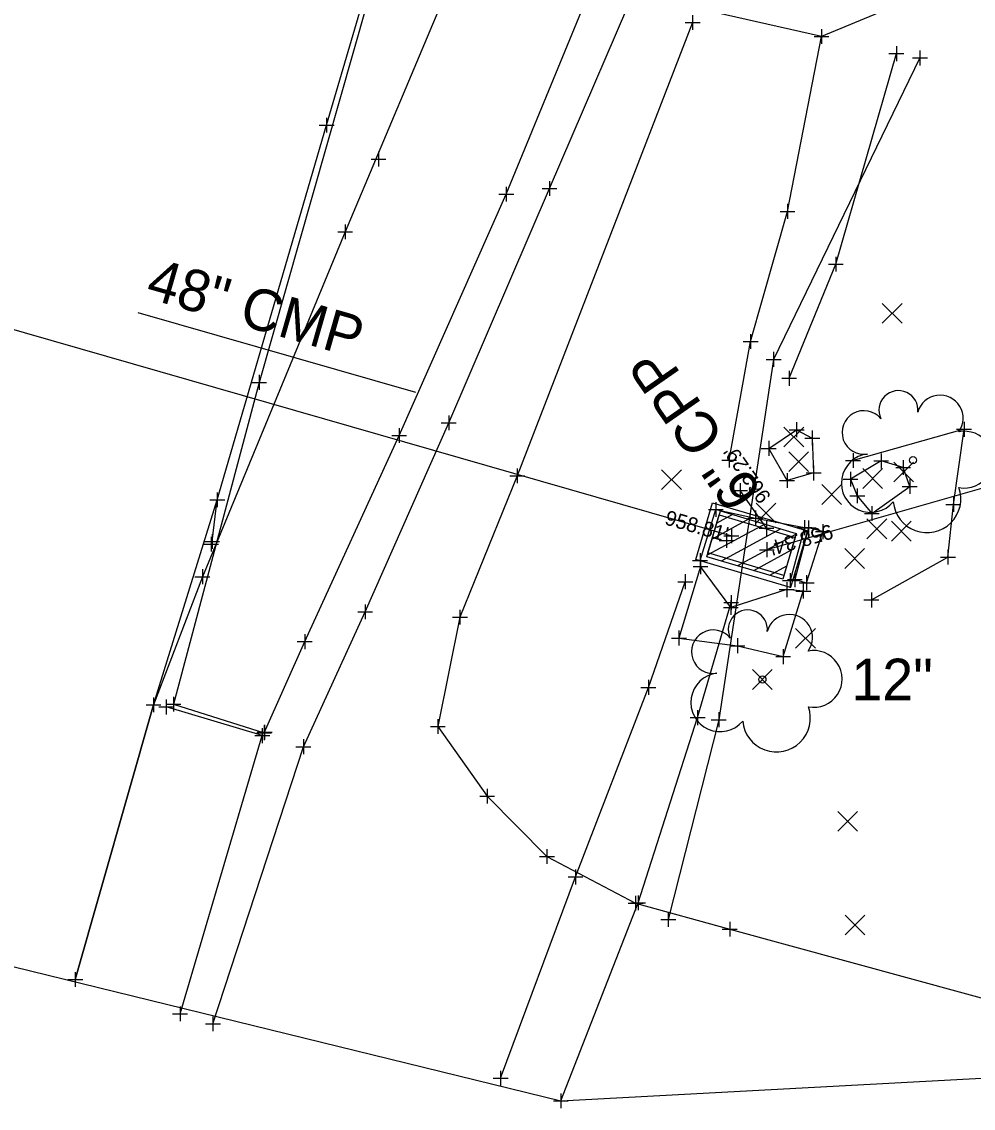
# Model space of a CAD drawing. Extents: x 160138 to 160780, y 488720 to 491073.
# Drawn here: x 160437.1 to 160501.3, y 489628.4 to 489701.6 of the extents above; entities that cross this region are included whole.
import ezdxf

# ---------------------------------------------------------------- set-up
doc = ezdxf.new("R2010")
doc.units = 0
for name, color, linetype in [('_CIVIL_CONSTRUCTION', 7, 'Continuous'), ('DR_X_Storm_Sewer', 7, 'Continuous'), ('DR_X_Text', 7, 'Continuous'), ('GE_X_Alignment_500_Bearings', 7, 'Continuous'), ('GE_X_Alignment_500_Stations', 7, 'Continuous'), ('PM_X_Dotted_Line', 7, 'Continuous'), ('PM_X_Lane_Line', 7, 'Continuous'), ('RD_X_Concrete_Pad', 7, 'Continuous'), ('RS_Raster1', 7, 'Continuous'), ('RW_X_CL', 7, 'Continuous'), ('RW_X_CL_100_Cardinal_Points', 7, 'Continuous'), ('RW_X_CL_100_Distances', 7, 'Continuous'), ('SC_Scratch1', 7, 'Continuous'), ('SV_P_Control_Cells_Set', 7, 'Continuous'), ('SV_P_Mon_Cells_Set', 7, 'Continuous'), ('SV_X_Control_Cells_Found', 7, 'Continuous'), ('SV_X_Random_Point', 7, 'Continuous'), ('SV_X_Terrain_Boundary', 7, 'Continuous'), ('UT_X_Electric', 7, 'Continuous'), ('VG_X_Text', 7, 'Continuous')]:
    doc.layers.add(name, color=color, linetype=linetype)

msp = doc.modelspace()

# ---------------------------------------------------------------- linework, layer by layer
at = {"layer": '_CIVIL_CONSTRUCTION'}
for p, q in [((160495.148, 489681.283), (160496.481, 489682.618)), ((160495.148, 489682.618), (160496.481, 489681.283)), ((160488.519, 489672.945), (160489.852, 489674.28)), ((160488.519, 489674.28), (160489.852, 489672.945)), ((160488.849, 489671.285), (160490.182, 489672.62)), ((160488.849, 489672.62), (160490.182, 489671.285)), ((160495.928, 489670.586), (160497.261, 489671.921)), ((160495.928, 489671.921), (160497.261, 489670.586)), ((160480.274, 489670.065), (160481.608, 489671.4)), ((160480.274, 489671.4), (160481.608, 489670.065)), ((160493.83, 489670.142), (160495.164, 489671.477)), ((160493.83, 489671.477), (160495.164, 489670.142)), ((160491.07, 489669.068), (160492.403, 489670.403)), ((160491.07, 489670.403), (160492.403, 489669.068)), ((160486.639, 489667.817), (160487.972, 489669.152)), ((160486.639, 489669.152), (160487.972, 489667.817)), ((160494.114, 489666.749), (160495.447, 489668.084)), ((160494.114, 489668.084), (160495.447, 489666.749)), ((160495.766, 489666.591), (160497.099, 489667.926)), ((160495.766, 489667.926), (160497.099, 489666.591)), ((160492.621, 489664.756), (160493.955, 489666.091)), ((160492.621, 489666.091), (160493.955, 489664.756)), ((160489.308, 489659.367), (160490.641, 489660.702)), ((160489.308, 489660.702), (160490.641, 489659.367)), ((160486.401, 489656.599), (160487.734, 489657.934)), ((160486.401, 489657.934), (160487.734, 489656.599)), ((160492.154, 489647.034), (160493.487, 489648.369)), ((160492.154, 489648.369), (160493.487, 489647.034)), ((160492.648, 489640.041), (160493.981, 489641.376)), ((160492.648, 489641.376), (160493.981, 489640.041))]:
    msp.add_line(p, q, dxfattribs=at)
at = {"layer": 'DR_X_Storm_Sewer'}
for p, q in [((160564.265, 489687.947), (160487.37, 489666.011)), ((160417.971, 489686.213), (160484.975, 489666.943)), ((160487.34, 489667.454), (160485.571, 489669.994))]:
    msp.add_line(p, q, dxfattribs=at)
at = {"layer": 'DR_X_Text'}
msp.add_line((160463.691, 489676.602), (160444.979, 489681.984), dxfattribs=at)
at = {"layer": 'GE_X_Alignment_500_Bearings'}
msp.add_lwpolyline([(160440.742, 489637.043), (160446.015, 489655.554), (160450.316, 489669.375), (160457.69, 489694.634), (160462.173, 489709.925)], dxfattribs=at)
at = {"layer": 'GE_X_Alignment_500_Stations'}
msp.add_lwpolyline([(160450.023, 489634.057), (160456.121, 489652.731), (160460.286, 489661.827), (160465.917, 489674.569), (160472.713, 489690.364), (160479.522, 489706.201)], dxfattribs=at)
at = {"layer": 'PM_X_Dotted_Line'}
msp.add_lwpolyline([(160449.962, 489666.566), (160450.316, 489669.375), (160457.69, 489694.634), (160462.173, 489709.925)], dxfattribs=at)
at = {"layer": 'PM_X_Lane_Line'}
msp.add_lwpolyline([(160468.561, 489710.284), (160458.933, 489687.435), (160449.314, 489664.193), (160446.015, 489655.554), (160440.742, 489637.043)], dxfattribs=at)
at = {"layer": 'RD_X_Concrete_Pad'}
for points in [[(160463.105, 489712.272), (160453.145, 489677.294), (160447.365, 489655.602), (160453.48, 489653.676), (160456.212, 489659.819), (160462.58, 489673.711), (160469.801, 489689.985), (160476.812, 489707.044)], [(160482.86, 489665.283), (160483.924, 489668.718), (160486.595, 489668.149), (160489.904, 489667.501), (160488.931, 489663.932)]]:
    msp.add_lwpolyline(points, dxfattribs=at)
for points in [[(160491.149, 489667.231), (160490.181, 489667.489), (160489.252, 489663.995), (160490.05, 489663.788)], [(160481.439, 489660.06), (160485.38, 489659.541), (160488.465, 489658.807), (160489.82, 489663.227), (160488.702, 489663.324), (160484.935, 489662.122), (160482.897, 489664.875)]]:
    msp.add_lwpolyline(points, close=True, dxfattribs=at)
at = {"layer": 'RS_Raster1'}
for p, q in [((160485.571, 489670.494), (160485.571, 489669.494)), ((160485.071, 489669.994), (160486.071, 489669.994)), ((160485.571, 489669.994), (160485.571, 489669.994)), ((160484.975, 489667.443), (160484.975, 489666.443)), ((160486.84, 489667.454), (160487.84, 489667.454)), ((160487.34, 489667.954), (160487.34, 489666.954)), ((160487.34, 489667.454), (160487.34, 489667.454)), ((160484.141, 489666.632), (160485.141, 489666.632)), ((160484.475, 489666.943), (160485.475, 489666.943)), ((160484.641, 489667.132), (160484.641, 489666.132)), ((160484.641, 489666.632), (160484.641, 489666.632)), ((160484.975, 489666.943), (160484.975, 489666.943)), ((160487.37, 489666.511), (160487.37, 489665.511)), ((160486.87, 489666.011), (160487.87, 489666.011)), ((160487.37, 489666.011), (160487.37, 489666.011))]:
    msp.add_line(p, q, dxfattribs=at)
at = {"layer": 'RW_X_CL'}
for p, q in [((160486.899, 489668.237), (160486.899, 489668.237)), ((160486.71, 489667.598), (160486.71, 489667.598)), ((160486.79, 489667.868), (160486.79, 489667.868)), ((160483.775, 489667.074), (160483.775, 489667.074)), ((160486.332, 489666.319), (160486.332, 489666.319)), ((160486.332, 489666.319), (160486.332, 489666.319)), ((160488.89, 489665.564), (160488.89, 489665.564)), ((160485.766, 489664.401), (160485.766, 489664.401)), ((160485.955, 489665.04), (160485.955, 489665.04))]:
    msp.add_line(p, q, dxfattribs=at)
at = {"layer": 'RW_X_CL_100_Cardinal_Points'}
msp.add_lwpolyline([(160497.686, 489699.16), (160487.825, 489678.845), (160484.123, 489654.553), (160480.721, 489641.083)], dxfattribs=at)
at = {"layer": 'RW_X_CL_100_Distances'}
for points in [[(160447.805, 489634.728), (160453.353, 489653.48), (160446.873, 489655.414)], [(160453.476, 489653.681), (160453.508, 489653.715)]]:
    msp.add_lwpolyline(points, dxfattribs=at)
at = {"layer": 'SC_Scratch1'}
for centre in [(160497.218, 489672.05), (160487.067, 489657.267)]:
    msp.add_circle(centre, 0.24, dxfattribs=at)
for centre, radius, start, end in [((160496.234, 489675.417), 1.317, 354.0047, 205.97412), ((160499.044, 489674.879), 1.553, 323.82996, 165.0376), ((160493.908, 489673.914), 1.471, 39.06254, 279.54124), ((160500.678, 489672.086), 1.915, 259.14531, 101.45961), ((160494.364, 489670.501), 1.974, 96.17219, 320.57371), ((160498.164, 489669.444), 2.284, 184.94757, 19.45715), ((160486.084, 489660.634), 1.317, 354.0047, 205.97412), ((160488.894, 489660.096), 1.553, 323.82996, 165.0376), ((160483.758, 489659.131), 1.471, 39.06254, 279.54124), ((160490.528, 489657.303), 1.915, 259.14531, 101.45961), ((160484.214, 489655.718), 1.974, 96.17219, 320.57371), ((160488.014, 489654.662), 2.284, 184.94757, 19.45715)]:
    msp.add_arc(centre, radius, start, end, dxfattribs=at)
at = {"layer": 'SV_P_Control_Cells_Set'}
for p, q in [((160491.054, 489700.611), (160491.054, 489700.611)), ((160484.82, 489672.048), (160484.82, 489672.048)), ((160484.82, 489672.048), (160484.82, 489672.048))]:
    msp.add_line(p, q, dxfattribs=at)
for points in [[(160484.82, 489672.048), (160486.271, 489680.045), (160488.755, 489688.822), (160491.054, 489700.611)], [(160494.414, 489662.624), (160499.576, 489665.518), (160499.94, 489669.066), (160500.658, 489674.13), (160493.177, 489672.028)], [(160469.416, 489630.383), (160474.463, 489643.955), (160479.378, 489656.734), (160481.869, 489663.857)]]:
    msp.add_lwpolyline(points, dxfattribs=at)
for points in [[(160488.725, 489670.681), (160487.489, 489672.842), (160489.372, 489674.101), (160490.427, 489673.541), (160490.521, 489671.189)], [(160493.003, 489670.767), (160493.461, 489669.647), (160494.442, 489668.457), (160496.994, 489670.27), (160496.56, 489671.554), (160495.074, 489671.997)]]:
    msp.add_lwpolyline(points, close=True, dxfattribs=at)
at = {"layer": 'SV_P_Mon_Cells_Set'}
for points in [[(160488.869, 489677.568), (160492.017, 489685.258), (160496.1, 489699.452)], [(160473.475, 489628.861), (160478.694, 489642.21), (160482.7, 489654.693), (160484.962, 489662.449)]]:
    msp.add_lwpolyline(points, dxfattribs=at)
at = {"layer": 'SV_X_Control_Cells_Found'}
for p, q in [((160486.137, 489668.061), (160483.67, 489666.719)), ((160485.051, 489668.381), (160483.99, 489667.804)), ((160487.222, 489667.74), (160483.349, 489665.634)), ((160488.307, 489667.42), (160484.295, 489665.238)), ((160489.334, 489667.068), (160485.38, 489664.917)), ((160489.014, 489665.983), (160486.465, 489664.597)), ((160488.693, 489664.898), (160487.55, 489664.276))]:
    msp.add_line(p, q, dxfattribs=at)
for points in [[(160488.963, 489663.457), (160482.569, 489665.345), (160483.702, 489669.181), (160490.096, 489667.293)], [(160488.433, 489664.016), (160483.318, 489665.526), (160484.232, 489668.623), (160489.347, 489667.112)], [(160488.512, 489664.285), (160483.397, 489665.796), (160484.153, 489668.353), (160489.267, 489666.842)]]:
    msp.add_lwpolyline(points, close=True, dxfattribs=at)
at = {"layer": 'SV_X_Random_Point'}
for p, q in [((160482.364, 489702.049), (160482.364, 489701.049)), ((160481.864, 489701.549), (160482.864, 489701.549)), ((160482.364, 489701.549), (160482.364, 489701.549)), ((160491.054, 489701.111), (160491.054, 489700.111)), ((160490.554, 489700.611), (160491.554, 489700.611)), ((160491.054, 489700.611), (160491.054, 489700.611)), ((160496.1, 489699.952), (160496.1, 489698.952)), ((160497.686, 489699.66), (160497.686, 489698.66)), ((160495.6, 489699.452), (160496.6, 489699.452)), ((160496.1, 489699.452), (160496.1, 489699.452)), ((160497.186, 489699.16), (160498.186, 489699.16)), ((160497.686, 489699.16), (160497.686, 489699.16)), ((160457.69, 489695.134), (160457.69, 489694.134)), ((160457.69, 489695.134), (160457.69, 489694.134)), ((160457.19, 489694.634), (160458.19, 489694.634)), ((160457.19, 489694.634), (160458.19, 489694.634)), ((160457.69, 489694.634), (160457.69, 489694.634)), ((160457.69, 489694.634), (160457.69, 489694.634)), ((160460.682, 489692.347), (160461.682, 489692.347)), ((160461.182, 489692.847), (160461.182, 489691.847)), ((160461.182, 489692.347), (160461.182, 489692.347)), ((160472.713, 489690.864), (160472.713, 489689.864)), ((160469.301, 489689.985), (160470.301, 489689.985)), ((160469.801, 489690.485), (160469.801, 489689.485)), ((160469.801, 489689.985), (160469.801, 489689.985)), ((160472.213, 489690.364), (160473.213, 489690.364)), ((160472.713, 489690.364), (160472.713, 489690.364)), ((160488.755, 489689.322), (160488.755, 489688.322)), ((160488.255, 489688.822), (160489.255, 489688.822)), ((160488.755, 489688.822), (160488.755, 489688.822)), ((160458.933, 489687.935), (160458.933, 489686.935)), ((160458.433, 489687.435), (160459.433, 489687.435)), ((160458.933, 489687.435), (160458.933, 489687.435)), ((160492.017, 489685.758), (160492.017, 489684.758)), ((160491.517, 489685.258), (160492.517, 489685.258)), ((160492.017, 489685.258), (160492.017, 489685.258)), ((160486.271, 489680.545), (160486.271, 489679.545)), ((160485.771, 489680.045), (160486.771, 489680.045)), ((160486.271, 489680.045), (160486.271, 489680.045)), ((160487.825, 489679.345), (160487.825, 489678.345)), ((160487.325, 489678.845), (160488.325, 489678.845)), ((160487.825, 489678.845), (160487.825, 489678.845)), ((160453.145, 489677.794), (160453.145, 489676.794)), ((160488.369, 489677.568), (160489.369, 489677.568)), ((160488.869, 489678.068), (160488.869, 489677.068)), ((160488.869, 489677.568), (160488.869, 489677.568)), ((160452.645, 489677.294), (160453.645, 489677.294)), ((160453.145, 489677.294), (160453.145, 489677.294)), ((160465.417, 489674.569), (160466.417, 489674.569)), ((160465.917, 489675.069), (160465.917, 489674.069)), ((160465.917, 489674.569), (160465.917, 489674.569)), ((160489.372, 489674.601), (160489.372, 489673.601)), ((160500.658, 489674.63), (160500.658, 489673.63)), ((160462.58, 489674.211), (160462.58, 489673.211)), ((160488.872, 489674.101), (160489.872, 489674.101)), ((160489.372, 489674.101), (160489.372, 489674.101)), ((160490.427, 489674.041), (160490.427, 489673.041)), ((160500.158, 489674.13), (160501.158, 489674.13)), ((160500.658, 489674.13), (160500.658, 489674.13)), ((160462.08, 489673.711), (160463.08, 489673.711)), ((160462.58, 489673.711), (160462.58, 489673.711)), ((160487.489, 489673.342), (160487.489, 489672.342)), ((160489.927, 489673.541), (160490.927, 489673.541)), ((160490.427, 489673.541), (160490.427, 489673.541)), ((160484.82, 489672.548), (160484.82, 489671.548)), ((160486.989, 489672.842), (160487.989, 489672.842)), ((160487.489, 489672.842), (160487.489, 489672.842)), ((160493.177, 489672.528), (160493.177, 489671.528)), ((160495.074, 489672.497), (160495.074, 489671.497)), ((160484.32, 489672.048), (160485.32, 489672.048)), ((160484.82, 489672.048), (160484.82, 489672.048)), ((160490.521, 489671.689), (160490.521, 489670.689)), ((160492.677, 489672.028), (160493.677, 489672.028)), ((160493.177, 489672.028), (160493.177, 489672.028)), ((160494.574, 489671.997), (160495.574, 489671.997)), ((160495.074, 489671.997), (160495.074, 489671.997)), ((160496.56, 489672.054), (160496.56, 489671.054)), ((160470.041, 489670.998), (160471.041, 489670.998)), ((160470.541, 489671.498), (160470.541, 489670.498)), ((160470.541, 489670.998), (160470.541, 489670.998)), ((160488.725, 489671.181), (160488.725, 489670.181)), ((160490.021, 489671.189), (160491.021, 489671.189)), ((160490.521, 489671.189), (160490.521, 489671.189)), ((160493.003, 489671.267), (160493.003, 489670.267)), ((160496.06, 489671.554), (160497.06, 489671.554)), ((160496.56, 489671.554), (160496.56, 489671.554)), ((160488.225, 489670.681), (160489.225, 489670.681)), ((160488.725, 489670.681), (160488.725, 489670.681)), ((160492.503, 489670.767), (160493.503, 489670.767)), ((160493.003, 489670.767), (160493.003, 489670.767)), ((160496.494, 489670.27), (160497.494, 489670.27)), ((160496.994, 489670.77), (160496.994, 489669.77)), ((160496.994, 489670.27), (160496.994, 489670.27)), ((160450.316, 489669.875), (160450.316, 489668.875)), ((160450.316, 489669.875), (160450.316, 489668.875)), ((160492.961, 489669.647), (160493.961, 489669.647)), ((160493.461, 489670.147), (160493.461, 489669.147)), ((160493.461, 489669.647), (160493.461, 489669.647)), ((160499.94, 489669.566), (160499.94, 489668.566)), ((160449.816, 489669.375), (160450.816, 489669.375)), ((160449.816, 489669.375), (160450.816, 489669.375)), ((160450.316, 489669.375), (160450.316, 489669.375)), ((160450.316, 489669.375), (160450.316, 489669.375)), ((160483.424, 489668.718), (160484.424, 489668.718)), ((160483.924, 489669.218), (160483.924, 489668.218)), ((160483.924, 489668.718), (160483.924, 489668.718)), ((160494.442, 489668.957), (160494.442, 489667.957)), ((160499.44, 489669.066), (160500.44, 489669.066)), ((160499.94, 489669.066), (160499.94, 489669.066)), ((160486.095, 489668.149), (160487.095, 489668.149)), ((160486.595, 489668.649), (160486.595, 489667.649)), ((160486.595, 489668.149), (160486.595, 489668.149)), ((160489.904, 489668.001), (160489.904, 489667.001)), ((160490.181, 489667.989), (160490.181, 489666.989)), ((160493.942, 489668.457), (160494.942, 489668.457)), ((160494.442, 489668.457), (160494.442, 489668.457)), ((160489.404, 489667.501), (160490.404, 489667.501)), ((160489.681, 489667.489), (160490.681, 489667.489)), ((160489.904, 489667.501), (160489.904, 489667.501)), ((160490.181, 489667.489), (160490.181, 489667.489)), ((160491.149, 489667.731), (160491.149, 489666.731)), ((160449.462, 489666.566), (160450.462, 489666.566)), ((160449.9, 489666.89), (160449.9, 489665.89)), ((160449.962, 489667.066), (160449.962, 489666.066)), ((160449.962, 489666.566), (160449.962, 489666.566)), ((160490.649, 489667.231), (160491.649, 489667.231)), ((160491.149, 489667.231), (160491.149, 489667.231)), ((160449.4, 489666.39), (160450.4, 489666.39)), ((160449.9, 489666.39), (160449.9, 489666.39)), ((160482.86, 489665.783), (160482.86, 489664.783)), ((160499.576, 489666.018), (160499.576, 489665.018)), ((160482.36, 489665.283), (160483.36, 489665.283)), ((160482.86, 489665.283), (160482.86, 489665.283)), ((160482.897, 489665.375), (160482.897, 489664.375)), ((160499.076, 489665.518), (160500.076, 489665.518)), ((160499.576, 489665.518), (160499.576, 489665.518)), ((160449.314, 489664.693), (160449.314, 489663.693)), ((160481.869, 489664.357), (160481.869, 489663.357)), ((160482.397, 489664.875), (160483.397, 489664.875)), ((160482.897, 489664.875), (160482.897, 489664.875)), ((160488.931, 489664.432), (160488.931, 489663.432)), ((160489.252, 489664.495), (160489.252, 489663.495)), ((160448.814, 489664.193), (160449.814, 489664.193)), ((160449.314, 489664.193), (160449.314, 489664.193)), ((160481.369, 489663.857), (160482.369, 489663.857)), ((160481.869, 489663.857), (160481.869, 489663.857)), ((160488.431, 489663.932), (160489.431, 489663.932)), ((160488.702, 489663.824), (160488.702, 489662.824)), ((160488.752, 489663.995), (160489.752, 489663.995)), ((160488.931, 489663.932), (160488.931, 489663.932)), ((160489.252, 489663.995), (160489.252, 489663.995)), ((160489.55, 489663.788), (160490.55, 489663.788)), ((160489.82, 489663.727), (160489.82, 489662.727)), ((160490.05, 489664.288), (160490.05, 489663.288)), ((160490.05, 489663.788), (160490.05, 489663.788)), ((160484.962, 489662.949), (160484.962, 489661.949)), ((160488.202, 489663.324), (160489.202, 489663.324)), ((160488.702, 489663.324), (160488.702, 489663.324)), ((160489.32, 489663.227), (160490.32, 489663.227)), ((160489.82, 489663.227), (160489.82, 489663.227)), ((160494.414, 489663.124), (160494.414, 489662.124)), ((160460.286, 489662.327), (160460.286, 489661.327)), ((160484.435, 489662.122), (160485.435, 489662.122)), ((160484.462, 489662.449), (160485.462, 489662.449)), ((160484.935, 489662.622), (160484.935, 489661.622)), ((160484.935, 489662.122), (160484.935, 489662.122)), ((160484.962, 489662.449), (160484.962, 489662.449)), ((160493.914, 489662.624), (160494.914, 489662.624)), ((160494.414, 489662.624), (160494.414, 489662.624)), ((160459.786, 489661.827), (160460.786, 489661.827)), ((160460.286, 489661.827), (160460.286, 489661.827)), ((160466.179, 489661.471), (160467.179, 489661.471)), ((160466.679, 489661.971), (160466.679, 489660.971)), ((160466.679, 489661.471), (160466.679, 489661.471)), ((160456.212, 489660.319), (160456.212, 489659.319)), ((160480.939, 489660.06), (160481.939, 489660.06)), ((160481.439, 489660.56), (160481.439, 489659.56)), ((160481.439, 489660.06), (160481.439, 489660.06)), ((160485.38, 489660.041), (160485.38, 489659.041)), ((160455.712, 489659.819), (160456.712, 489659.819)), ((160456.212, 489659.819), (160456.212, 489659.819)), ((160484.88, 489659.541), (160485.88, 489659.541)), ((160485.38, 489659.541), (160485.38, 489659.541)), ((160488.465, 489659.307), (160488.465, 489658.307)), ((160487.965, 489658.807), (160488.965, 489658.807)), ((160488.465, 489658.807), (160488.465, 489658.807)), ((160479.378, 489657.234), (160479.378, 489656.234)), ((160478.878, 489656.734), (160479.878, 489656.734)), ((160479.378, 489656.734), (160479.378, 489656.734)), ((160445.515, 489655.554), (160446.515, 489655.554)), ((160445.515, 489655.554), (160446.515, 489655.554)), ((160446.015, 489656.054), (160446.015, 489655.054)), ((160446.015, 489656.054), (160446.015, 489655.054)), ((160446.015, 489655.554), (160446.015, 489655.554)), ((160446.015, 489655.554), (160446.015, 489655.554)), ((160446.865, 489655.602), (160447.865, 489655.602)), ((160446.873, 489655.914), (160446.873, 489654.914)), ((160447.365, 489656.102), (160447.365, 489655.102)), ((160447.365, 489655.602), (160447.365, 489655.602)), ((160446.373, 489655.414), (160447.373, 489655.414)), ((160446.873, 489655.414), (160446.873, 489655.414)), ((160482.7, 489655.193), (160482.7, 489654.193)), ((160484.123, 489655.053), (160484.123, 489654.053)), ((160453.476, 489654.181), (160453.476, 489653.181)), ((160453.48, 489654.176), (160453.48, 489653.176)), ((160453.508, 489654.215), (160453.508, 489653.215)), ((160464.682, 489654.101), (160465.682, 489654.101)), ((160465.182, 489654.601), (160465.182, 489653.601)), ((160465.182, 489654.101), (160465.182, 489654.101)), ((160482.2, 489654.693), (160483.2, 489654.693)), ((160482.7, 489654.693), (160482.7, 489654.693)), ((160483.623, 489654.553), (160484.623, 489654.553)), ((160484.123, 489654.553), (160484.123, 489654.553)), ((160452.853, 489653.48), (160453.853, 489653.48)), ((160452.976, 489653.681), (160453.976, 489653.681)), ((160452.98, 489653.676), (160453.98, 489653.676)), ((160453.008, 489653.715), (160454.008, 489653.715)), ((160453.353, 489653.98), (160453.353, 489652.98)), ((160453.353, 489653.48), (160453.353, 489653.48)), ((160453.476, 489653.681), (160453.476, 489653.681)), ((160453.48, 489653.676), (160453.48, 489653.676)), ((160453.508, 489653.715), (160453.508, 489653.715)), ((160455.621, 489652.731), (160456.621, 489652.731)), ((160456.121, 489653.231), (160456.121, 489652.231)), ((160456.121, 489652.731), (160456.121, 489652.731)), ((160468.511, 489649.896), (160468.511, 489648.896)), ((160468.011, 489649.396), (160469.011, 489649.396)), ((160468.511, 489649.396), (160468.511, 489649.396)), ((160472.044, 489645.328), (160473.044, 489645.328)), ((160472.544, 489645.828), (160472.544, 489644.828)), ((160472.544, 489645.328), (160472.544, 489645.328)), ((160473.963, 489643.955), (160474.963, 489643.955)), ((160474.463, 489644.455), (160474.463, 489643.455)), ((160474.463, 489643.955), (160474.463, 489643.955)), ((160478.518, 489642.682), (160478.518, 489641.682)), ((160478.694, 489642.71), (160478.694, 489641.71)), ((160478.018, 489642.182), (160479.018, 489642.182)), ((160478.194, 489642.21), (160479.194, 489642.21)), ((160478.518, 489642.182), (160478.518, 489642.182)), ((160478.694, 489642.21), (160478.694, 489642.21)), ((160480.221, 489641.083), (160481.221, 489641.083)), ((160480.721, 489641.583), (160480.721, 489640.583)), ((160480.721, 489641.083), (160480.721, 489641.083)), ((160484.862, 489640.929), (160484.862, 489639.929)), ((160484.362, 489640.429), (160485.362, 489640.429)), ((160484.862, 489640.429), (160484.862, 489640.429)), ((160440.742, 489637.543), (160440.742, 489636.543)), ((160440.742, 489637.543), (160440.742, 489636.543)), ((160440.242, 489637.043), (160441.242, 489637.043)), ((160440.242, 489637.043), (160441.242, 489637.043)), ((160440.742, 489637.043), (160440.742, 489637.043)), ((160440.742, 489637.043), (160440.742, 489637.043)), ((160447.805, 489635.228), (160447.805, 489634.228)), ((160447.305, 489634.728), (160448.305, 489634.728)), ((160447.805, 489634.728), (160447.805, 489634.728)), ((160450.023, 489634.557), (160450.023, 489633.557)), ((160449.523, 489634.057), (160450.523, 489634.057)), ((160450.023, 489634.057), (160450.023, 489634.057)), ((160469.416, 489630.883), (160469.416, 489629.883)), ((160468.916, 489630.383), (160469.916, 489630.383)), ((160469.416, 489630.383), (160469.416, 489630.383)), ((160473.475, 489629.361), (160473.475, 489628.361)), ((160472.975, 489628.861), (160473.975, 489628.861)), ((160473.475, 489628.861), (160473.475, 489628.861))]:
    msp.add_line(p, q, dxfattribs=at)
at = {"layer": 'SV_X_Terrain_Boundary'}
msp.add_lwpolyline([(160560.406, 489729.318), (160491.054, 489700.611), (160398.91, 489721.406), (160369.477, 489735.484), (160345.102, 489741.595), (160340, 489741.437), (160332.016, 489740.129), (160312.105, 489734.793), (160313.355, 489709.705), (160316.289, 489695.424), (160319.472, 489684.931), (160347.565, 489655.198), (160408.831, 489644.698), (160473.475, 489628.861), (160504.758, 489630.54), (160514.912, 489637.894), (160547.865, 489638.238)], dxfattribs=at)
at = {"layer": 'UT_X_Electric'}
msp.add_lwpolyline([(160482.364, 489701.549), (160470.541, 489670.998), (160466.679, 489661.471), (160465.182, 489654.101), (160468.511, 489649.396), (160472.544, 489645.328), (160478.518, 489642.182), (160484.862, 489640.429), (160509.06, 489633.828)], dxfattribs=at)

# ---------------------------------------------------------------- texts
at = {"layer": 'DR_X_Text'}
for s, rotation, p in [('48" CMP', 343.95446, (160445.394, 489683.011)), ('6" CPP', 124.86088, (160487.129, 489669.937))]:
    msp.add_text(s, height=2.8, rotation=rotation, dxfattribs=at).set_placement(p)
at = {"layer": 'SC_Scratch1'}
for s, rotation, p in [("962.29'", 124.86088, (160487.688, 489669.587)), ("958.81'", 343.95446, (160480.418, 489667.733)), ("958.34'", 195.92163, (160491.655, 489667.753))]:
    msp.add_text(s, height=1, rotation=rotation, dxfattribs=at).set_placement(p)
at = {"layer": 'VG_X_Text'}
msp.add_text('12"', height=2.8, dxfattribs=at).set_placement((160493.067, 489655.867))

doc.saveas('drawing.dxf')
